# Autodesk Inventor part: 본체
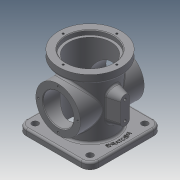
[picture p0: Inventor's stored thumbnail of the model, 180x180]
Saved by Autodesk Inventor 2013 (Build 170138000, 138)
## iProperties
Created: 2021-03
Part Number: 본체
Material: 일반
Document SubType Name: Modeling
Designer: a
Density: 1 g/cm^3
Author: a
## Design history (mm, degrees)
sketch "스케치2"
  geometry: L1 (0, 55.5)-(0, -55.5); L2 (0, 55.5)-(-38, 55.5); L3 (-38, 55.5)-(-38, -55.5); L4 (-38, -55.5)-(0, -55.5); 2 further points
  constraints: 8 end point, 3 perpendicular, 1 coincident, 1 midpoint, 1 vertical
  dimensions: "d2" = 111 distance of L1.start L1.end; "d3" = 38 distance of L1.start L2.end
revolve "회전1" sketch "스케치2" stored, may be unused: angle "d4" = 90 deg
sketch "스케치3"
  geometry: C1 r 38 at (0, 0) reference; 1 further point
  constraints: 1 coincident
hole "구멍1" sketch "스케치3" at (0, 0) diameter "d5" = 66; stored, may be unused: countersink angle "d9" = 90 deg, drill point angle "d11" = 118 deg; dims "d6" = 6, "d7" = 74, "d8" = 7, "d10" = 8
sketch "스케치4"
  geometry: C1 r 38 at (0, 0) reference; C2 r 49 at (0, 0)
  constraints: 1 centre point, 1 coincident
  dimensions: "d12" = 98 diameter of C2
extrude "돌출1" join sketch "스케치4" distance "d13" = 13; taper "d14" = 0 deg
node "작업 평면1"
sketch "스케치6"
  geometry: L1 (38, -55.5)-(-38, -55.5) reference; L2 (0, -55.5)-(0, -1.5); C1 r 35 at (0, -1.5); 1 further point
  constraints: 2 end point, 1 centre point, 1 coincident, 1 midpoint, 1 perpendicular
  dimensions: "d88" = 54 distance of L2.start L2.end; "d89" = 70 diameter of C1
extrude "돌출2" join sketch "스케치6" stored distance "d17" = 13; taper "d18" = 0 deg
sketch "스케치9"
  geometry: L1 (43, -57)-(-43, -57); L2 (-57, -43)-(-57, 43); L3 (-43, 57)-(43, 57); L4 (57, 43)-(57, -43); L5 (57, -57)-(-57, 57); L6 (-57, -57)-(57, 57); C1 r 38 at (0, 0) reference; A1 r 14 centre (-43, 43) between (-43, 57) and (-57, 43); A2 r 14 centre (43, 43) between (57, 43) and (43, 57); A3 r 14 centre (-43, -43) between (-57, -43) and (-43, -57); A4 r 14 centre (43, -43) between (43, -57) and (57, -43)
  constraints: 12 end point, 8 point on circle, 8 point on line, 8 tangent, 4 centre point, 3 equal radius, 2 midpoint, 2 parallel, 1 horizontal, 1 perpendicular
  dimensions: "d34" = 114 distance of L5.end L6.end; "d35" = 114 distance of L6.start L5.end; "d36" = 14 radius of A1
extrude "돌출4" join sketch "스케치9" distance "d37" = 10; taper "d38" = 0 deg
sketch "스케치10"
  geometry: A1 r 14 centre (43, -43) between (43, -57) and (57, -43) reference; A2 r 14 centre (43, 43) between (57, 43) and (43, 57) reference; A3 r 14 centre (-43, 43) between (-43, 57) and (-57, 43) reference; A4 r 14 centre (-43, -43) between (-57, -43) and (-43, -57) reference; 4 further points
  constraints: 4 coincident
hole "구멍3" sketch "스케치10" at (-43, 43), (43, 43), (43, -43), (-43, -43) diameter "d39" = 10; stored, may be unused: countersink angle "d43" = 90 deg, drill point angle "d45" = 0 deg; dims "d40" = 6, "d41" = 74, "d42" = 7, "d44" = 8
node "작업 평면3"
sketch "스케치11"
  geometry: L1 (-14.5, -7)-(14.5, -7); L2 (14.5, -7)-(14.5, 7); L3 (14.5, 7)-(-14.5, 7); L4 (-14.5, 7)-(-14.5, -7); L5 (-14.5, -7)-(14.5, 7); L6 (14.5, -7)-(-14.5, 7); 1 further point
  constraints: 12 end point, 2 midpoint, 2 parallel, 1 horizontal, 1 perpendicular
  dimensions: "d50" = 29 distance of L3.end L2.end; "d52" = 14 distance of L1.end L2.end
extrude "돌출5" join sketch "스케치11" stored distance "d53" = 10; taper "d54" = 0 deg
feature "면 기울기1" dims angle "d55" = 15 deg
feature "면 기울기2" dims angle "d56" = 15 deg
sketch "스케치12"
  geometry: L1 (7, 14.5)-(-7, 14.5) reference; L2 (-7, -14.5)-(7, -14.5) reference; 3 further points
  constraints: 2 horizontal alignment, 2 midpoint, 4 other
extrude "돌출6" join sketch "스케치12" stored distance "d61" = 0; taper "d62" = 15 deg
sketch "스케치13"
  geometry: A1 r 7 centre (0, -14.5) between (-7, -14.5) and (7, -14.5) reference; A2 r 7 centre (0, 14.5) between (7, 14.5) and (-7, 14.5) reference; 3 further points
  constraints: 2 coincident
hole "구멍4" sketch "스케치13" at (0, 14.5), (0, -14.5) diameter "d63" = 4.134; stored, may be unused: countersink angle "d67" = 90 deg, drill point angle "d69" = 118 deg; dims "d64" = 8, "d65" = 74, "d66" = 7, "d68" = 10
sketch "스케치14"
  geometry: L1 (0, 0)-(0, 42); C1 r 37 at (0, 0) reference; 1 further point
  constraints: 2 end point, 1 coincident, 1 vertical
  dimensions: "d70" = 42 distance of L1.start L1.end
hole "구멍5" sketch "스케치14" at (0, 42) diameter "d71" = 3.242; stored, may be unused: countersink angle "d75" = 90 deg, drill point angle "d77" = 118 deg; dims "d72" = 6, "d73" = 74, "d74" = 7, "d76" = 8
fillet "모깎기1" dims "d81" = 3
chamfer "모따기1" distance "d82" = 1; stored, may be unused: second distance "d83" = 2, angle "d84" = 45 deg
sketch "스케치15"
  geometry: C1 r 41 at (0, 0) reference; C2 r 50 at (0, 0)
  constraints: 1 centre point, 1 coincident, 1 other
  dimensions: "d85" = 100 diameter of C2
feature "엠보싱1" sketch "스케치15" dims "d18" = 0, "d86" = 0.5, "d87" = 0
sketch "스케치16"
  geometry: L1 (0, 0)-(0, 31); C1 r 35 at (0, 0) reference; 2 further points
  constraints: 2 end point, 1 coincident, 1 vertical
  dimensions: "d90" = 31 distance of L1.start L1.end
hole "구멍6" sketch "스케치16" at (0, 31) diameter "d91" = 3.242; stored, may be unused: countersink angle "d95" = 90 deg, drill point angle "d97" = 118 deg; dims "d92" = 6, "d93" = 74, "d94" = 7, "d96" = 8
sketch "스케치17"
  geometry: C1 r 35 at (0, 0) reference; C2 r 24 at (0, 0); 1 further point
  constraints: 1 centre point, 1 coincident
  dimensions: "d101" = 48 diameter of C2
extrude "돌출7" cut sketch "스케치17" stored distance "d102" = 10; taper "d103" = 0 deg
chamfer "모따기2" distance "d104" = 1; stored, may be unused: second distance "d105" = 2, angle "d106" = 45 deg
fillet "모깎기2" dims "d107" = 3
node "솔리드1"
mirror "대칭1"
pattern_circular "원형 패턴2" dims angle "d79" = 360 deg
pattern_circular "원형 패턴3" dims angle "d99" = 360 deg
mirror "대칭2"
other parameters: "d46" = 55
